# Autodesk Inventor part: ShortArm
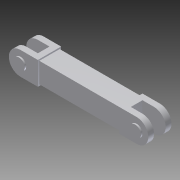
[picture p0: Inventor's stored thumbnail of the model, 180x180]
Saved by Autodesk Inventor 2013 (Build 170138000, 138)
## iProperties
Created: 2004-11
Document SubType Name: Modeling
Designer: Autodesk, Inc.
Manufacturer: Standard
Standards Organization: Custom
Description: SWING ARM, SHORT ARM
Mass: 540.311 g
Surface Area: 666.42 cm^2
Volume: 540.311 cm^3
Density: 1 g/cm^3
Material: Allgemein
CAGE: 1LJX3
Dept. ID: Product Design
Description #2: ---
Finish #1: ---
Finish #2: ---
Material ID: ---
Project Number: ---
Author: Autodesk, Inc.
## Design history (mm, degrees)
sketch "Sketch1"
  geometry: L1 (0, 25.4)-(254, 25.4); L2 (254, 25.4)-(254, -25.4); L3 (254, -25.4)-(0, -25.4); L4 (0, -25.4)-(0, 25.4); 3 further points
  constraints: 8 end point, 2 midpoint, 2 parallel, 2 vertical alignment, 1 coincident, 1 horizontal, 1 perpendicular, 4 other
  dimensions: "d0" = 254 distance of L1.start L1.end; "d1" = 50.8 distance of L1.end L2.end
extrude "Extrusion1" new body sketch "Sketch1" stored distance "d2" = 50.8; taper "d3" = 0 deg
sketch "Sketch2"
  geometry: L1 (-25.4, 50.8)-(-25.4, 0) reference; L2 (-25.4, 50.8)-(0, 50.8) reference; L3 (0, 0)-(-25.4, 0) reference; L4 (0, 0)-(254, 0) reference; L5 (254, 50.8)-(0, 50.8) reference; L6 (-25.4, 12.7)-(25.4, 12.7); L7 (25.4, 12.7)-(25.4, 38.1); L8 (25.4, 38.1)-(-25.4, 38.1); L9 (-25.4, 38.1)-(-25.4, 12.7); 2 further points
  constraints: 8 end point, 2 midpoint, 2 parallel, 1 coincident, 1 horizontal, 1 perpendicular, 1 point on line
  dimensions: "d4" = 25.4 distance of L6.end L7.end; "d10" = 50.8 distance of L7.end L8.end
extrude "Extrusion2" cut sketch "Sketch2" stored distance "d5" = 50.8; taper "d6" = 0 deg
workplane "Work Plane1"
workplane "Work Plane2"
workplane "Work Plane3"
sketch "Sketch5"
  geometry: L1 (0, 25.4)-(254, 25.4) reference; L2 (254, -25.4)-(0, -25.4) reference; L3 (38.1, 25.4)-(38.1, -25.4); L4 (215.9, 25.4)-(215.9, -25.4); C1 r 25.4 at (0, 0); C2 r 25.4 at (254, 0); A1 r 25.4 centre (254, 0) between (254, -25.4) and (254, 25.4) reference; A2 r 25.4 centre (0, 0) between (0, 25.4) and (0, -25.4) reference
  constraints: 4 end point, 4 point on line, 2 centre point, 2 coincident, 2 concentric, 2 perpendicular
  dimensions: "d11" = 12.7 distance edge to line of C1 L3; "d13" = 12.7 distance edge to line of C2 L4 (= d11)
extrude "Extrusion4" cut sketch "Sketch5" distance "d14" = 3.175; taper "d15" = 0 deg
pattern_circular "Circular Pattern1" dims angle "d18" = 360 deg
mirror "Mirror1"
sketch "Sketch3"
  geometry: C1 r 12.7 at (0, 0); C2 r 12.7 at (254, 0); A1 r 25.4 centre (0, 0) between (0, 25.4) and (0, -25.4) reference; A2 r 25.4 centre (254, 0) between (254, -25.4) and (254, 25.4) reference
  constraints: 2 centre point, 2 coincident, 1 equal radius
  dimensions: "d7" = 25.4 diameter of C1
extrude "Extrusion3" join sketch "Sketch3" distance "d8" = 3.175; taper "d9" = 0 deg
mirror "Mirror2"
body "Solid1"
node "Projected Loop1"
